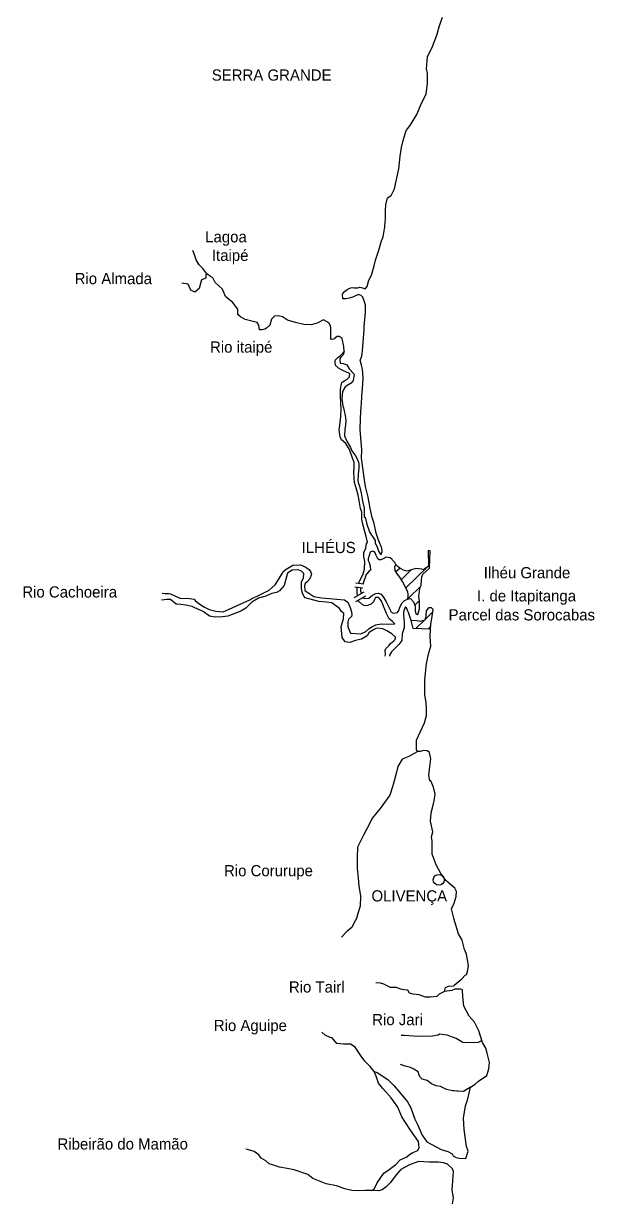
# Model space of a CAD drawing. Extents: x 662444 to 1640468, y 7452018 to 9606170.
# Drawn here: x 1120077 to 1153949, y 8319713 to 8389481 of the extents above; entities that cross this region are included whole.
import ezdxf

# ---------------------------------------------------------------- set-up
doc = ezdxf.new("R2010")
doc.units = 0
for name, color, linetype in [('Level 1', 7, 'Continuous'), ('Level 2', 7, 'Continuous'), ('Level 3', 7, 'Continuous')]:
    doc.layers.add(name, color=color, linetype=linetype)

msp = doc.modelspace()

# ---------------------------------------------------------------- linework, layer by layer
at = {"layer": 'Level 1'}
for points in [[(1141132, 8358168), (1141278, 8357964), (1141347, 8358129), (1141332, 8358352), (1141159, 8358790), (1141119, 8358891), (1140998, 8359239), (1140883, 8359809), (1140763, 8360180), (1140647, 8360705), (1140514, 8361376), (1140368, 8362014), (1140285, 8362539), (1140214, 8363130), (1140131, 8363688), (1140145, 8364210), (1140046, 8365381), (1140075, 8366069), (1140104, 8366769), (1140119, 8366925), (1140141, 8367358), (1140214, 8368079), (1140224, 8368456), (1140195, 8368969), (1140125, 8369204), (1140057, 8369506), (1140069, 8369539), (1140150, 8369737), (1140191, 8370070), (1140289, 8371335), (1140294, 8371501), (1140354, 8372145), (1140360, 8372356), (1140371, 8372778), (1140280, 8373036), (1140199, 8373239), (1140115, 8373341), (1139954, 8373412), (1139648, 8373275), (1139396, 8373193), (1139222, 8373153), (1139027, 8373147), (1139002, 8373426), (1139114, 8373579), (1139280, 8373697), (1139444, 8373781), (1139564, 8373811), (1139683, 8373808), (1139900, 8373803), (1139965, 8373812), (1140019, 8373833), (1140181, 8373795), (1140342, 8373747), (1140465, 8373888), (1140572, 8374252), (1140721, 8374559), (1140876, 8375111), (1140950, 8375443), (1141160, 8376027), (1141315, 8376590), (1141408, 8376832), (1141497, 8377308), (1141510, 8377408), (1141541, 8377763), (1141543, 8377841), (1141558, 8378385), (1141566, 8378719), (1141675, 8379149), (1141895, 8379277), (1142079, 8379673), (1142337, 8380856), (1142422, 8381610), (1142500, 8382119), (1142598, 8382550), (1142776, 8383135), (1142877, 8383255), (1143079, 8383538), (1143408, 8384086), (1143696, 8384757), (1143970, 8385283), (1144052, 8385948), (1144035, 8386516), (1143977, 8386796), (1144039, 8387506), (1144347, 8388109), (1144603, 8388781), (1144736, 8389289), (1144771, 8389399), (1144935, 8389862)], [(1139096, 8370021), (1139082, 8370310), (1138987, 8370791), (1138859, 8370872), (1138795, 8370907), (1138676, 8370921), (1138499, 8370781), (1138488, 8370748), (1138336, 8370730), (1138315, 8370764), (1138312, 8371053), (1138300, 8371443), (1138272, 8371588), (1138199, 8371723), (1137879, 8371910), (1137495, 8371708), (1137135, 8371607), (1136703, 8371618), (1136208, 8371753), (1135746, 8371876), (1135448, 8372084), (1135190, 8372147), (1134962, 8372119), (1134784, 8371935), (1134688, 8371593), (1134489, 8371409), (1134400, 8371344), (1134237, 8371315), (1134085, 8371308), (1134027, 8371577), (1133945, 8371745), (1133612, 8371821), (1133235, 8371920), (1132958, 8372083), (1132799, 8372209), (1132792, 8372365), (1132797, 8372543), (1132472, 8372940), (1132217, 8373147), (1132069, 8373284), (1131885, 8373711), (1131441, 8374123), (1131308, 8374394), (1131169, 8374475), (1130956, 8374625), (1130705, 8374943), (1130505, 8375159), (1130328, 8375453), (1130248, 8375700), (1130197, 8375823), (1130126, 8376014)], [(1130956, 8374625), (1130890, 8374571), (1130885, 8374371), (1130644, 8374266), (1130584, 8374056), (1130501, 8373758), (1130235, 8373543), (1130000, 8373660), (1129836, 8374020), (1129459, 8374074)], [(1139956, 8356264), (1140231, 8356824), (1140303, 8357100), (1140326, 8357556), (1140268, 8357835), (1140264, 8358102), (1140379, 8358355), (1140419, 8358621), (1140486, 8358708), (1140398, 8359044), (1140231, 8359704), (1140144, 8360085), (1140144, 8360496), (1140063, 8360699), (1139989, 8361190), (1139922, 8361503), (1139823, 8361850), (1139714, 8362254), (1139664, 8362800), (1139695, 8363177), (1139691, 8363433), (1139570, 8363759), (1139420, 8364207), (1139202, 8364569), (1138948, 8364787), (1138855, 8364956), (1138812, 8365369), (1138815, 8365502), (1138898, 8366167), (1138920, 8366600), (1138907, 8366923), (1138877, 8367458), (1138886, 8367780), (1138949, 8368112), (1138962, 8368189), (1139105, 8368275), (1139248, 8368360), (1139414, 8368511), (1139441, 8368722), (1139280, 8368770), (1138981, 8368912), (1138757, 8369040), (1138640, 8369143), (1138609, 8369166), (1138559, 8369334), (1138563, 8369512), (1138730, 8369663), (1138763, 8369685), (1138874, 8369782), (1139096, 8370021), (1139037, 8369833), (1138870, 8369626), (1138836, 8369572), (1138862, 8369326), (1139045, 8369310), (1139249, 8369238), (1139394, 8368990), (1139668, 8368693), (1139699, 8368659), (1139636, 8368294), (1139513, 8368153), (1139271, 8368014), (1139138, 8367884), (1139002, 8367655), (1138969, 8367244), (1139012, 8366798), (1139052, 8366675), (1139101, 8366507), (1139159, 8366216), (1139195, 8365937), (1139187, 8365637), (1139138, 8365416), (1139116, 8365016), (1139259, 8364701), (1139477, 8364328), (1139558, 8364126), (1139778, 8363831), (1139850, 8363696), (1139941, 8363460), (1139970, 8363314), (1139974, 8363081), (1139950, 8362981), (1139913, 8362382), (1139920, 8362248), (1140000, 8362024), (1140109, 8361620), (1140183, 8361151), (1140280, 8360726), (1140288, 8360626), (1140295, 8360459), (1140279, 8360293), (1140287, 8360192), (1140342, 8360191), (1140450, 8359788), (1140611, 8359316), (1140725, 8359135), (1140776, 8359045), (1140932, 8358807), (1140940, 8358674), (1141083, 8358381), (1141132, 8358168)], [(1140204, 8355413), (1140332, 8355365), (1140571, 8355392), (1140781, 8355564), (1140968, 8355659), (1141120, 8355677), (1141291, 8355617), (1141448, 8355402), (1141593, 8355164), (1141726, 8354894), (1141839, 8354657), (1141869, 8354568), (1142008, 8354497), (1142258, 8354535), (1142337, 8354666), (1142396, 8354854), (1142533, 8355117), (1142688, 8355246), (1142853, 8355331), (1143026, 8355360), (1143216, 8355177), (1143307, 8354907), (1143310, 8354640), (1143359, 8354450), (1143477, 8354413), (1143562, 8354756), (1143564, 8355212), (1143538, 8355479), (1143594, 8355956), (1143675, 8356154), (1143694, 8356465), (1143710, 8356654), (1143768, 8356808), (1144157, 8357165), (1144195, 8358187), (1144088, 8358223), (1144106, 8357288), (1143797, 8357074), (1143701, 8357110), (1143355, 8357141), (1143094, 8357071), (1142821, 8357000), (1142628, 8357050), (1142404, 8357167), (1142298, 8357247), (1142172, 8357384), (1142110, 8357497), (1141962, 8357646), (1141942, 8357691), (1141825, 8357772), (1141588, 8357811), (1141412, 8357727), (1141281, 8357664), (1141183, 8357666), (1141098, 8357724), (1140996, 8357927), (1140945, 8358073), (1140904, 8358141), (1140775, 8358178), (1140644, 8358125), (1140514, 8357717), (1140522, 8357628), (1140573, 8357505), (1140643, 8357280), (1140658, 8357046), (1140570, 8356971), (1140447, 8356841), (1140403, 8356786), (1140215, 8356224)], [(1141528, 8351952), (1141543, 8352063), (1141538, 8352274), (1141574, 8352407), (1141751, 8352569), (1141852, 8352700), (1142040, 8352862), (1142129, 8352937), (1142143, 8353070), (1141921, 8353265), (1141623, 8353451), (1141388, 8353568), (1141227, 8353595), (1141021, 8353612), (1140769, 8353474), (1140559, 8353324), (1140468, 8353148), (1140128, 8352957), (1139769, 8352878), (1139441, 8352764), (1139150, 8352794), (1138984, 8353054), (1138925, 8353701), (1139067, 8354164), (1139076, 8354486), (1138949, 8354590), (1138813, 8354782), (1138368, 8355117), (1138055, 8355147), (1137591, 8355193), (1136785, 8355414), (1136722, 8355483), (1136619, 8355674), (1136561, 8355954), (1136572, 8356343), (1136686, 8356585), (1136704, 8356851), (1136567, 8356999), (1136374, 8357060), (1136017, 8357058), (1135741, 8356865), (1135682, 8356655), (1135549, 8356147), (1135271, 8355832), (1135117, 8355747), (1135084, 8355726), (1134801, 8355656), (1134396, 8355488), (1134015, 8355387), (1133619, 8355153), (1133274, 8354795), (1132967, 8354614), (1132191, 8354323), (1131887, 8354276), (1131454, 8354254), (1131109, 8354318), (1130738, 8354606), (1130246, 8354819), (1130075, 8354901), (1129709, 8354967), (1129407, 8355008), (1129170, 8355025), (1129137, 8355026), (1128787, 8355302)], [(1128796, 8355646), (1129352, 8355387), (1129925, 8355361), (1130194, 8355321), (1130268, 8355241), (1130469, 8355080), (1130809, 8354849), (1131087, 8354708), (1131495, 8354608), (1131916, 8354575), (1132267, 8354733), (1132705, 8354933), (1133493, 8355290), (1133625, 8355364), (1133986, 8355522), (1134655, 8355871), (1134999, 8356184), (1135449, 8356873), (1135484, 8356961), (1135661, 8357112), (1136057, 8357346), (1136512, 8357367), (1136790, 8357238), (1137013, 8357098), (1137128, 8356929), (1137157, 8356817), (1137063, 8356530), (1136896, 8356357), (1136786, 8356259), (1136750, 8356127), (1136764, 8355849), (1137306, 8355478), (1137758, 8355400), (1138234, 8355376), (1138665, 8355320), (1139119, 8355286), (1139310, 8355147), (1139453, 8354843), (1139543, 8354574), (1139560, 8354396), (1139525, 8354296), (1139348, 8354134), (1139322, 8353990), (1139314, 8353690), (1139467, 8353319), (1140082, 8353270), (1140378, 8353417), (1140577, 8353579), (1140786, 8353707), (1140972, 8353802), (1141299, 8353860), (1141720, 8353849), (1142100, 8353872), (1141941, 8354021), (1141772, 8354170), (1141618, 8354474), (1141354, 8355115), (1141334, 8355182), (1141187, 8355375), (1141145, 8355421), (1140962, 8355426), (1140905, 8355316), (1140836, 8355173), (1140725, 8355054), (1140506, 8354960), (1140343, 8354942), (1140193, 8354990), (1139918, 8355253)], [(1142853, 8355331), (1142899, 8355441), (1142893, 8355619), (1142875, 8355753), (1142700, 8356114), (1142567, 8356384), (1142401, 8356644), (1142265, 8356815), (1142130, 8357030), (1142103, 8357242), (1142172, 8357384)], [(1142171, 8356962), (1142393, 8357178)], [(1142494, 8356497), (1143072, 8357060)], [(1142762, 8356001), (1144029, 8357235)], [(1140269, 8356223), (1139794, 8356280)], [(1142908, 8355385), (1143652, 8356110)], [(1128300, 8355689), (1128483, 8355662), (1128699, 8355657), (1128796, 8355646)], [(1140267, 8355745), (1139673, 8355404)], [(1140208, 8355991), (1139734, 8356048)], [(1140358, 8355509), (1139765, 8355169)], [(1139882, 8355521), (1139877, 8355722), (1139869, 8355833), (1139863, 8356033)], [(1140089, 8355994), (1140067, 8355961), (1140066, 8355906), (1140063, 8355806), (1140124, 8355659)], [(1128787, 8355302), (1128571, 8355308), (1128257, 8355271)], [(1143989, 8351508), (1144122, 8352143), (1144238, 8352536), (1144210, 8353093), (1144212, 8353549), (1144241, 8353837), (1144343, 8354413), (1144384, 8354723), (1144289, 8354814), (1144105, 8354819), (1143970, 8354645), (1143940, 8354334), (1143890, 8354080), (1143607, 8354010), (1143413, 8354037), (1143079, 8354068), (1142907, 8354529), (1142877, 8354619), (1142806, 8354810), (1142721, 8354856), (1142639, 8354636), (1142615, 8354537), (1142611, 8354370), (1142665, 8353979), (1142658, 8353713), (1142667, 8353634), (1142538, 8353271), (1142528, 8352882), (1142337, 8352631), (1142092, 8352382), (1141904, 8352209), (1141790, 8352012), (1141792, 8351945)], [(1143287, 8354975), (1143564, 8355245)], [(1144212, 8353549), (1143185, 8353598), (1143079, 8354068)], [(1143347, 8353594), (1143836, 8354070)], [(1143902, 8354124), (1144369, 8354579)], [(1144093, 8353552), (1144226, 8353682)], [(1143988, 8348828), (1143966, 8349218), (1143880, 8349643), (1143878, 8350013), (1143884, 8350537), (1143989, 8351508)], [(1141401, 8326289), (1141139, 8326607), (1140999, 8327033), (1140877, 8327304), (1141059, 8327243), (1141686, 8326837), (1142043, 8326471), (1142389, 8326084), (1142860, 8325515), (1143045, 8325143), (1143297, 8324480), (1143471, 8324130), (1143736, 8323534), (1143995, 8323137), (1144847, 8322669), (1145254, 8322558), (1145499, 8322418), (1145572, 8322305), (1145753, 8322211), (1145913, 8322162), (1146313, 8322151), (1146454, 8322570), (1146354, 8322850), (1146219, 8323866), (1146184, 8324546), (1146290, 8325266), (1146408, 8325607), (1146516, 8326016), (1146601, 8326369), (1146876, 8326551), (1147076, 8326735), (1147561, 8327066), (1147690, 8327463), (1147722, 8327840), (1147576, 8328400), (1147508, 8328691), (1147301, 8329031), (1147082, 8329715), (1146837, 8330233), (1146511, 8330598), (1146203, 8331174), (1146132, 8331765), (1146121, 8332155), (1146025, 8332191), (1145766, 8332198), (1145657, 8332190), (1145493, 8332116), (1145048, 8332050), (1145049, 8332062), (1145109, 8332294), (1145284, 8332367), (1145598, 8332391), (1145631, 8332424), (1146074, 8332801), (1146275, 8333018), (1146384, 8333071), (1146385, 8333115), (1146421, 8333225), (1146474, 8333591), (1146352, 8334273), (1146230, 8334543), (1146104, 8335091), (1145887, 8335475), (1145669, 8336182), (1145610, 8336406), (1145532, 8336720), (1145473, 8336955), (1145634, 8337295), (1145753, 8337681), (1145761, 8337981), (1145658, 8338184), (1145140, 8338632), (1144828, 8339063), (1144560, 8339571), (1144318, 8340200), (1144328, 8340589), (1144317, 8340968), (1144281, 8341235), (1144364, 8341533), (1144230, 8342160), (1144254, 8342660), (1144361, 8343024), (1144446, 8343366), (1144500, 8343754), (1144403, 8344179), (1144240, 8344551), (1144175, 8344552), (1144130, 8344865), (1144187, 8345375), (1144243, 8345852), (1144167, 8346232), (1144029, 8346336), (1143823, 8346341), (1143617, 8346291), (1143476, 8346284), (1143392, 8346397), (1143386, 8346954), (1143604, 8347448), (1143868, 8347986), (1143988, 8348428), (1143988, 8348828)], [(1143476, 8346284), (1143256, 8346168), (1142938, 8345998), (1142545, 8345842), (1142284, 8345393), (1142199, 8345073), (1142113, 8344686), (1141971, 8344200), (1141805, 8343693), (1141233, 8342919), (1141043, 8342679), (1140785, 8342353), (1140421, 8341673), (1140273, 8341377), (1139884, 8340609), (1139868, 8339997), (1139873, 8339363), (1139922, 8338784), (1139974, 8338315), (1140066, 8337712), (1140050, 8337123), (1139919, 8336671), (1139825, 8336384), (1139677, 8336110), (1139562, 8335847), (1139275, 8335632), (1139264, 8335621), (1138941, 8335285)], [(1145048, 8332050), (1144741, 8331892), (1144597, 8331751), (1144229, 8331717), (1143915, 8331725), (1143540, 8331847), (1143196, 8331901), (1142981, 8331951), (1142867, 8332132), (1142640, 8332149), (1142447, 8332199), (1142212, 8332283), (1141855, 8332293), (1141449, 8332482), (1141257, 8332554), (1140976, 8332561)], [(1140877, 8327304), (1140647, 8327599), (1140332, 8327919), (1140113, 8328225), (1139760, 8328746), (1139473, 8328932), (1139062, 8328932), (1138674, 8328965), (1138381, 8329306), (1138262, 8329320), (1137974, 8329462), (1137773, 8329634)], [(1147239, 8329132), (1147052, 8329026), (1146770, 8329001), (1146133, 8329018), (1145751, 8329262), (1145205, 8329466), (1144752, 8329512), (1144675, 8329469), (1144349, 8329400), (1143690, 8329385), (1143214, 8329398), (1142686, 8329434), (1142480, 8329440)], [(1146601, 8326369), (1146173, 8326114), (1145849, 8326145), (1145774, 8326147), (1145633, 8326151), (1145525, 8326154), (1145171, 8326242), (1144809, 8326418), (1144561, 8326447), (1144273, 8326577), (1144029, 8326773), (1143729, 8326859), (1143623, 8326951), (1143541, 8327098), (1143481, 8327289), (1143237, 8327451), (1143034, 8327545), (1142712, 8327621), (1142445, 8327717)], [(1145526, 8319459), (1145579, 8319802), (1145516, 8320271), (1145552, 8320815), (1145578, 8321370), (1145518, 8321528), (1145234, 8321802), (1144998, 8321887), (1144675, 8321918), (1144146, 8321932), (1143509, 8321961), (1142985, 8321775), (1142470, 8321488), (1142180, 8321174), (1141855, 8320727), (1141566, 8320445), (1141357, 8320295), (1141139, 8320235), (1140707, 8320246), (1140871, 8320320), (1141054, 8320693), (1141448, 8321272), (1141778, 8321496), (1142165, 8321797), (1142431, 8322068), (1142825, 8322246), (1142970, 8322387), (1143178, 8322492), (1143462, 8322618), (1143543, 8322805), (1143509, 8323151), (1143031, 8323831), (1142522, 8324612), (1142290, 8325197), (1141883, 8325753), (1141401, 8326289)], [(1140707, 8320246), (1140340, 8320256), (1140037, 8320231), (1139562, 8320255), (1139132, 8320345), (1138651, 8320525), (1138028, 8320642), (1137247, 8320952), (1136941, 8321194), (1136138, 8321471), (1135708, 8321561), (1135267, 8321639), (1134849, 8321762), (1134656, 8321822), (1134456, 8322006), (1134180, 8322169), (1134034, 8322362), (1133758, 8322558), (1133426, 8322667), (1133275, 8322693)]]:
    msp.add_lwpolyline(points, dxfattribs=at)
at = {"layer": 'Level 2'}
msp.add_ellipse((1144709, 8338677), major_axis=(324, -9), ratio=0.999997, dxfattribs=at)

# ---------------------------------------------------------------- texts
at = {"layer": 'Level 3'}
for s, height, p in [('SERRA GRANDE', 664.63, (1131241, 8386092)), ('Lagoa', 664.4, (1130853, 8376496)), ('Itaipé', 664.3, (1131250, 8375398)), ('Rio Almada', 664.2, (1123109, 8374018)), ('Rio itaipé', 664.2, (1131141, 8369956)), ('ILHÉUS', 663.9, (1136578, 8358064)), ('Ilhéu Grande', 664.01, (1147381, 8356569)), ('Rio Cachoeira', 663.68, (1120004, 8355427)), ('I. de Itapitanga', 663.98, (1146982, 8355195)), ('Parcel das Sorocabas', 663.95, (1145295, 8354067)), ('Rio Corurupe', 663.35, (1131971, 8338891)), ('OLIVENÇA', 663.4, (1140720, 8337394)), ('Rio Tairl', 663.2, (1135820, 8331992)), ('Rio Aguipe', 663.1, (1131366, 8329706)), ('Rio Jari', 663.2, (1140763, 8330055)), ('Ribeirão do Mamão', 662.81, (1122095, 8322678))]:
    msp.add_text(s, height=height, dxfattribs=at).set_placement(p)

doc.saveas('drawing.dxf')
